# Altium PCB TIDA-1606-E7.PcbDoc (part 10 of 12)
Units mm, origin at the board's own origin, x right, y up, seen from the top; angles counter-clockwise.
Board outline 270 x 345 mm, 4 copper layers (Top Layer, Signal Layer 1, Signal Layer 2, Bottom Layer), stack 2.326 mm thick; 1282 components, 576 nets, 3628 pads, 4132 vias.
Unrouted connection lines stored in the file: 1719.
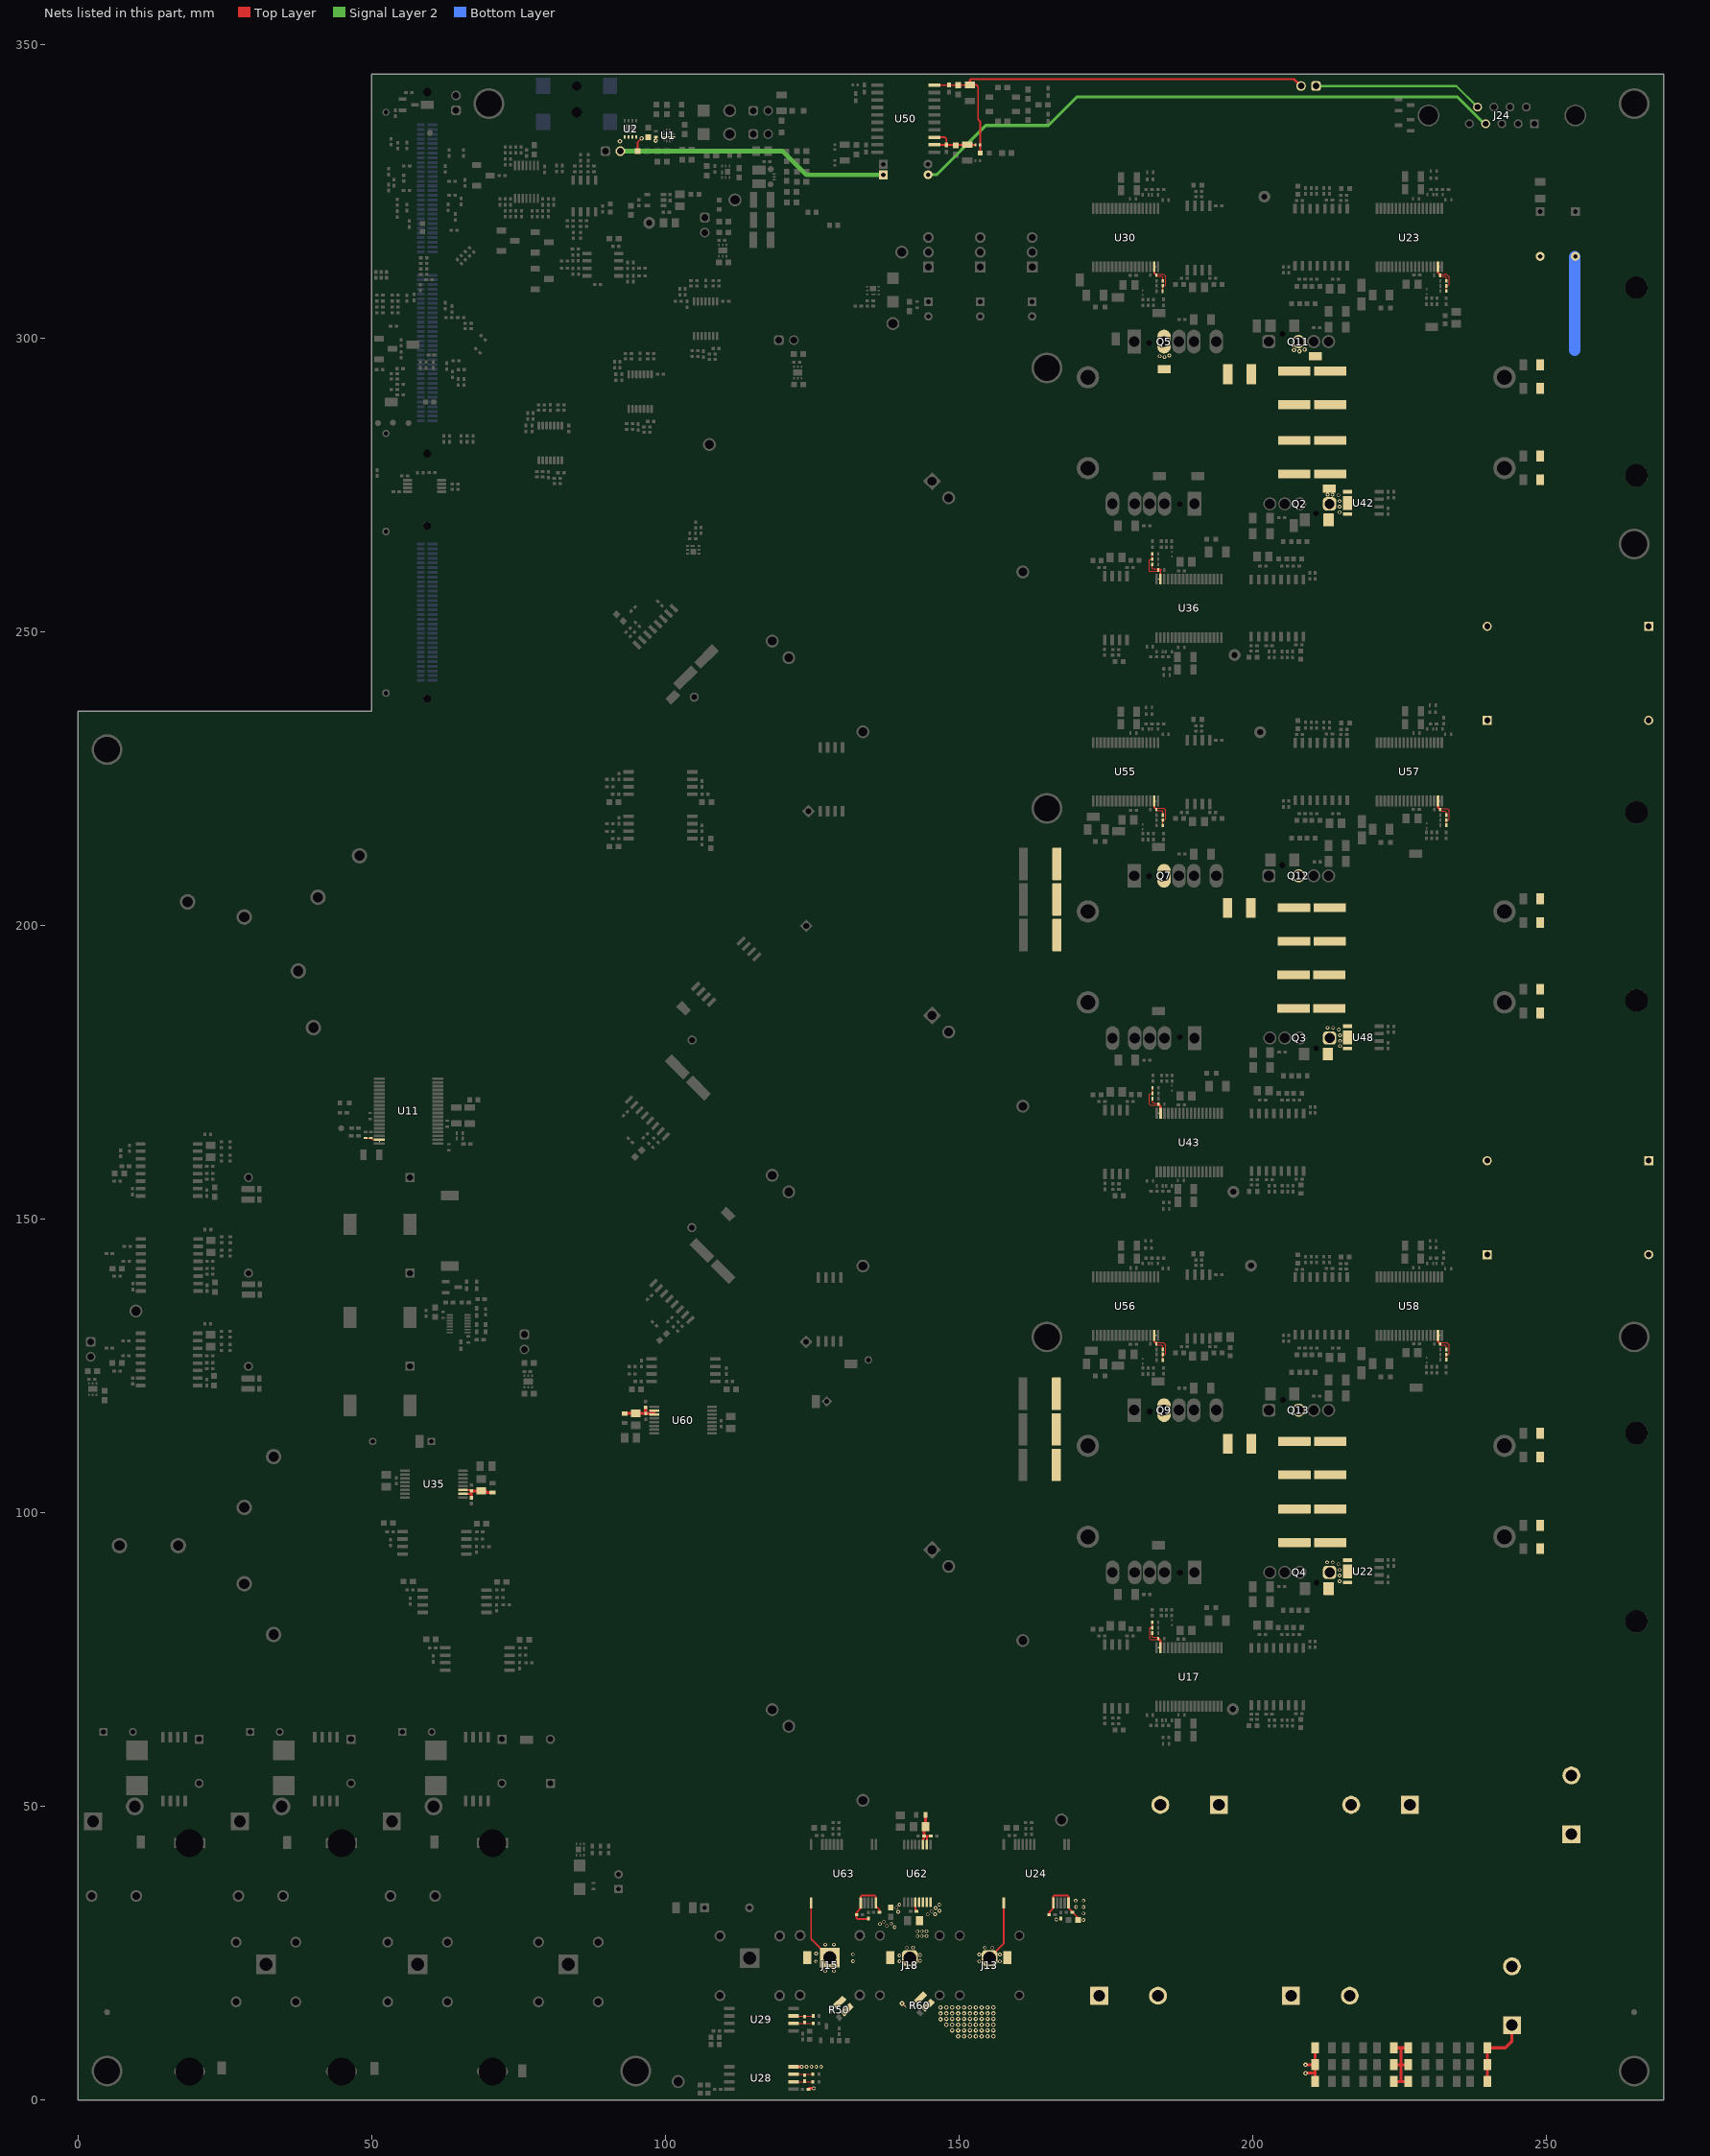
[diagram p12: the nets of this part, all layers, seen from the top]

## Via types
v1: diameter 0.762, hole 0.356, Top Layer to Bottom Layer, tented both sides, 2905 vias
v2: diameter 0.61, hole 0.356, Top Layer to Bottom Layer, tented both sides, 1212 vias
v3: diameter 0.864, hole 0.406, Top Layer to Bottom Layer, tented both sides, 15 vias

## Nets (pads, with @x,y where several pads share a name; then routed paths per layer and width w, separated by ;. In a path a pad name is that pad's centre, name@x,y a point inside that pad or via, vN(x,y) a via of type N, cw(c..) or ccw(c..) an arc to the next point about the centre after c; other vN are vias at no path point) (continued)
VDC+: C36.2 C37.2 C38.2 C39.2 C40.2 C41.2 C42.2 C43.2 C44.2 C45.2 C395.2 D8.1 D15.1 D17.1 J13.1 Q2.1 Q3.1 Q4.1 R41.2 R42.2 R43.2 TP29.1 TP65.1 U22.5 U22.6 U22.7 U24.1 U42.5 U42.6 U42.7 U48.5 U48.6 U48.7 | length 19.3
  Top Layer w0.305: J13.1@155.243,24.249 157.651,26.657 U24.1@157.651,33.6
  Top Layer w0.508: v1(209.05,4.594) 209.082,4.626 210.647,4.626 ; v1(209.05,6.06) R43.2@210.647,6.06 ; R41.2@210.647,3.192 210.647,4.626 ; R42.2@210.647,8.928 R43.2@210.647,6.06 ; 210.647,4.626 R43.2@210.647,6.06
  other v2: 154.619,22.5 155.918,22.5 153.5,23.639 157,23.639 153.5,24.841 157,24.841 154.451,26 155.75,26 214.853,88.39 214.853,89.354 214.853,90.295 214.653,91.295 212.729,91.595 213.67,91.595 214.921,179.498 214.921,180.393 214.921,181.334 214.718,182.334 212.793,182.634 213.734,182.634 214.853,270.432 214.853,271.359 214.853,272.3 214.653,273.3 212.795,273.412 213.639,273.412
VDC-: C46.1 C47.1 C48.1 C49.1 C50.1 C51.1 C52.1 C53.1 C54.1 C55.1 C396.1 C458.1 C459.1 C460.1 J4.2 Q11.2 Q12.2 Q13.2 R57.1 R58.1 R59.1 R60.I1 TP60.1 | length 29
  Top Layer w0.508: R57.1@239.992,3.192 R59.1@239.992,6.06 R58.1@239.992,8.928 243.044,8.928 244.189,10.073 C51.1@244.189,12.802
  Bottom Layer w2: 254.868,298.019 J4.2@254.868,313.9
  other v1: 149.9,10.9 150.9,10.895 151.9,10.9 152.9,10.901 153.9,10.901 154.9,10.9 155.9,10.9 148.892,11.9 149.9,11.9 150.9,11.895 151.9,11.9 152.9,11.901 153.9,11.901 154.9,11.9 155.9,11.9 147.9,12.857 148.892,12.863 149.9,12.863 150.9,12.857 151.9,12.863 152.9,12.864 153.9,12.864 154.9,12.863 155.9,12.863 146.9,13.8 147.9,13.857 150.9,13.857 148.892,13.863 149.9,13.863 151.9,13.863 152.9,13.864 153.9,13.864 154.9,13.863 155.9,13.863 146.9,14.8 147.9,14.795 148.892,14.8 149.9,14.8 150.9,14.795 151.9,14.8 152.9,14.801 153.9,14.801 154.9,14.8 155.9,14.8 146.9,15.8 147.9,15.795 148.892,15.8 149.9,15.8 150.9,15.795 151.9,15.8 152.9,15.801 153.9,15.801 154.9,15.8 155.9,15.8 208,297.846 207.077,298.046 208.896,298.133
VDC-_REF: C35.1 C176.1 C177.2 C222.2 C286.2 C446.2 C454.1 C456.1 C457.2 NT9.1 R21.2 R31.2 U24.2 U24.6 U28.4 U62.12 U62.13 U62.14 U62.15 U62.16 U63.2 U63.6 | length 27.2
  Top Layer w0.254: v1(140.348,16.5) NT9.1@140.82,16.027 ; U62.12@142.627,33.705 142.627,32.374 C286.2@142.801,32.2
  Top Layer w0.305: R31.2@132.598,31.5 132.598,31 132.698,30.9 C454.1@134.599,30.9 ; R31.2@132.598,31.582 132.598,31.974 133.298,32.674 U63.2@133.298,33.6 133.298,34.7 133.498,34.9 135.673,34.9 135.899,34.674 U63.6@135.899,33.6 135.899,33.073 136.498,32.474 C457.2@136.498,32 ; R21.2@165.4,31.582 165.4,31.974 166.1,32.674 U24.2@166.1,33.6 166.1,34.7 166.3,34.9 168.475,34.9 168.701,34.674 U24.6@168.701,33.6 168.701,32.715 170.301,31.115 C176.1@170.301,30.7 ; C35.1@167.401,30.9 C35.1@167.401,30.956
  Top Layer w0.5: U28.4@121.85,5.697 v2(123.283,5.697) ; C222.2@124.413,1.9 124.545,2.032 v2(125.349,2.032)
  other v2: 124.102,5.697 124.921,5.697 125.74,5.697 126.559,5.697 142.976,27.96 143.716,27.96 144.5,27.96 142.976,28.781 143.716,28.781 144.5,28.781 139.092,29.465 137.774,29.684 136.598,30 138.481,30.1 137.277,30.409 171.247,30.709 166.6,30.799 144.722,31.638 145.992,31.689 171.247,31.806 139.678,32.083 145.379,32.222 146.703,32.248 146.05,32.766 139.392,32.788 169.972,32.903 171.247,32.903 139.906,33.34 146.678,33.34 169.919,34 171.247,34
VDC_MID: C36.1 C37.1 C38.1 C39.1 C40.1 C41.1 C42.1 C43.1 C44.1 C45.1 C46.2 C47.2 C48.2 C49.2 C50.2 C51.2 C52.2 C53.2 C54.2 C55.2 C67.2 C71.2 C72.2 C73.2 C75.2 C76.2 C395.1 C396.2 C458.2 C459.2 C460.2 J5.2 Q5.2 Q7.2 Q9.2 R47.1 R48.1 R49.1 R50.I1 R51.2 R52.2 R53.2 R117.1 R118.1 R119.1 R120.1 R121.1 R122.1 R123.1 R124.1 R125.1 R126.1 R127.1 R128.1 TP33.1 | length 13.1
  Top Layer w0.508: R47.1@224.09,3.192 225.417,3.192 ; R49.1@224.09,6.06 225.31,6.06 ; R48.1@224.09,8.928 225.31,8.928 ; R51.2@226.542,3.192 225.417,3.192 ; R53.2@226.542,6.06 225.31,6.06 ; R52.2@226.542,8.928 225.31,8.928 ; 225.31,6.06 225.31,8.928 ; 225.31,6.06 225.31,3.299 225.417,3.192
  other v2: 185.039,296.841 184.226,297.002 185.826,297.099
VDC_MID_IN: J15.1 R50.I2 TP66.1 U63.1 | length 10.7
  Top Layer w0.305: U63.1@124.849,33.6 124.86,33.589 124.86,27.479 J15.1@128.065,24.274
  other v2: 127.287,22 128.728,22 125.691,23.621 131.985,23.666 131.985,24.867 125.729,25.004 127.287,26.522 128.726,26.522
VDC_NEG_IN: J18.1 R60.I2 TP67.1
  other v2: 141.203,22.497 142.325,22.5 139.906,23.666 143.406,23.75 139.906,24.665 143.406,24.75 141.203,26 142.231,26
VEEA_MID1: C244.2 C245.2 NT20.2 R256.1 R257.1 U30.35 | length 8.2
  Top Layer w0.203: R257.1@184.715,308.049 C245.2@184.715,308.976 185.093,308.976 185.2,309.083 185.2,310.602 184.828,310.974 183.842,310.974 C244.2@183.644,310.776 183.825,310.595 184.51,310.595 184.715,310.389 R256.1@184.715,309.818
  Top Layer w0.305: U30.35@183.278,312.215 183.278,311.142 C244.2@183.644,310.776
VEEA_MID2: C403.2 C404.2 NT23.2 R505.1 R506.1 U55.35 | length 8.2
  Top Layer w0.203: R506.1@184.717,217.104 C404.2@184.717,218.008 185.019,218.008 185.2,218.189 185.2,219.716 184.916,220 183.839,220 C403.2@183.646,219.807 183.838,219.615 183.838,219.6 184.626,219.6 184.717,219.509 R505.1@184.717,218.85
  Top Layer w0.305: U55.35@183.28,221.247 183.28,220.173 C403.2@183.646,219.807
VEEA_MID3: C411.2 C412.2 NT24.2 R513.1 R514.1 U56.35 | length 8.1
  Top Layer w0.203: R514.1@184.717,126.04 C412.2@184.717,127.013 185.053,127.013 185.2,127.16 185.2,128.6 184.8,129 183.834,129 C411.2@183.646,128.812 183.858,128.6 184.5,128.6 184.717,128.383 R513.1@184.717,127.855
  Top Layer w0.305: U56.35@183.28,130.251 183.28,129.178 C411.2@183.646,128.812
VEEA_SN_L1: C288.2 C289.2 NT21.2 R285.1 R286.1 U36.35 | length 8.7
  Top Layer w0.203: R285.1@182.942,261.535 182.942,260.798 183.757,260.798 C288.2@183.958,260.598 ; C289.2@182.942,262.373 182.464,262.373 182.464,260.398 183.758,260.398 C288.2@183.958,260.598 ; C289.2@182.943,262.468 R286.1@182.943,263.334 ; R286.1@182.99,263.21 R286.1@182.995,263.205 ; C288.2@183.961,260.6 C288.2@183.958,260.598
  Top Layer w0.305: U36.35@184.324,259.035 184.324,260.6
  Top Layer w0.4: C288.2@183.961,260.6 184.324,260.6
VEEA_SN_L2: C331.2 C332.2 NT22.2 R324.1 R325.1 U43.35 | length 8.3
  Top Layer w0.203: R324.1@182.984,170.569 182.984,170.028 183.188,169.823 183.808,169.823 C331.2@184,169.632 183.837,169.469 182.673,169.469 182.48,169.663 182.48,171.348 182.591,171.459 C332.2@182.984,171.459 ; C332.2@182.986,171.459 R325.1@182.986,172.405
  Top Layer w0.4: C331.2@184,169.632 184.366,169.266 U43.35@184.366,168.069
VEEA_SN_L3: C144.2 C145.2 NT18.2 R155.1 R156.1 U17.35 | length 8.3
  Top Layer w0.203: R155.1@182.944,79.572 182.944,78.921 183.035,78.829 183.765,78.829 C144.2@183.96,78.634 183.798,78.472 182.679,78.472 182.504,78.647 182.504,80.462 C145.2@182.945,80.462 R156.1@182.945,81.4
  Top Layer w0.4: C144.2@183.96,78.634 184.326,78.268 U17.35@184.326,77.074
VEEA_UCC_AEF: C93.2 NT17.2 R40.1 U11.35 | length 2.4
  Top Layer w0.203: R40.1@49.011,163.855 C93.2@49.9,163.855 50.184,163.571 U11.35@51.343,163.571
VEEA_VDC-1: C184.2 C185.2 NT19.2 R194.1 R195.1 U23.35 | length 7.9
  Top Layer w0.203: R195.1@233.012,308.095 C185.2@233.012,308.958 233.298,308.958 233.5,309.16 233.5,310.447 232.985,310.962 232.135,310.962 231.973,310.8 232.165,310.608 232.165,310.6 232.757,310.6 233.012,310.345 R194.1@233.012,309.803
  Top Layer w0.305: U23.35@231.607,312.215 231.607,311.166 C184.2@231.973,310.8
VEEA_VDC-2: C419.2 C420.2 NT25.2 R533.1 R534.1 U57.35 | length 8
  Top Layer w0.203: C420.2@233.014,217.127 R534.1@233.014,217.989 233.32,217.989 233.512,218.181 233.512,219.61 233.165,219.957 232.151,219.957 C419.2@231.975,219.781 232.184,219.572 232.802,219.572 233.014,219.36 R533.1@233.014,218.834
  Top Layer w0.4: U57.35@231.609,221.247 231.609,220.147 C419.2@231.975,219.781
VEEA_VDC-3: C427.2 C428.2 NT26.2 R541.1 R542.1 U58.35 | length 8.1
  Top Layer w0.203: R542.1@233.014,126.132 C428.2@233.014,126.994 233.394,126.994 233.5,127.1 233.5,128.628 233.128,129 232.19,129 C427.2@231.975,128.786 232.161,128.6 232.792,128.6 233.014,128.378 R541.1@233.014,127.839
  Top Layer w0.305: U58.35@231.609,130.251 231.609,129.152 C427.2@231.975,128.786
VIN_PWR: C1.1 C2.1 J1.2 J22.1 R1.2 U1.5 U2.1 U2.2 U2.3 U2.4 | length 48.9
  Top Layer w0.305: R1.2@95.302,331.9 95.302,333.381 v1(96.002,334.081) ; C2.1@98.602,334.292 C2.1@98.611,334.3
  Signal Layer 2 w0.762: J1.2@92.372,331.9 120.059,331.9 124.066,327.893 J22.1@137.16,327.893
  other v1: 92.302,333.6 98.414,333.707
VIN_PWR_CAN: J22.2 J24.4 | length 102.4
  Signal Layer 2 w0.508: J22.2@144.78,327.603 145.07,327.893 146.216,327.893 154.611,336.288 165.27,336.288 170.12,341.138 234.895,341.138 239.465,336.568 J24.4@239.718,336.568
VINN_DC-: C224.2 R243.2 U28.3 | length 3.3
  Top Layer w0.203: U28.3@121.85,4.427 R243.2@125.176,4.427
VINN_VMD: C273.2 R275.1 U29.3 | length 3.4
  Top Layer w0.203: U29.3@121.85,14.36 R275.1@125.218,14.36
VINP_DC-: C224.1 R238.2 U28.2 | length 3.3
  Top Layer w0.203: U28.2@121.85,3.157 123.771,3.157 123.78,3.166 123.828,3.119 R238.2@125.176,3.119
VINP_DC-_HAVOK: C292.1 C346.1 L11.1 R23.1 U62.2 U62.3 | length 7.8
  Top Layer w0.305: C292.1@144.085,45.014 144.577,45.014 ; U62.2@144.577,43.555 144.577,45.014 ; R23.1@145.242,45 145.228,45.014 144.577,45.014
  Top Layer w0.35: U62.3@143.927,43.555 143.927,44.425 144.085,44.582 C292.1@144.085,45.014
  Top Layer w0.5: C292.1@144.085,45.014 144.085,46.343 C346.1@144.342,46.6 L11.1@144.342,48.6
VINP_PCC_HAVOK: C285.1 C448.1 L14.1 R247.1 U35.2 U35.3 | length 7.8
  Top Layer w0.305: U35.2@65.56,103.275 67.02,103.275
  Top Layer w0.35: U35.3@65.56,103.925 66.862,103.925 C448.1@67.02,103.767 67.02,103.275 R247.1@67.02,102.61
  Top Layer w0.5: C448.1@67.02,103.767 68.348,103.767 69.433,103.767 69.69,103.51 L14.1@70.605,103.51
VINP_SN_HAVOK: C363.1 C364.1 L12.1 R76.1 U60.2 U60.3 | length 6.8
  Top Layer w0.35: U60.3@97.992,116.958 U60.3@98.15,116.8 U60.2@98.15,117.45
  Top Layer w0.5: L12.1@93.1,116.958 C364.1@95,116.958 C363.1@96.691,116.958 ; R76.1@96.68,118 96.68,116.969 C363.1@96.691,116.958 ; U60.3@97.992,116.958 C363.1@96.691,116.958
VINP_VMD: C273.1 R271.1 U29.2 | length 3.4
  Top Layer w0.203: U29.2@121.85,13.09 R271.1@125.218,13.09
VISOOUT: C380.1 C381.1 C382.1 FB18.1 U50.12 U50.13 | length 10.2
  Top Layer w0.305: U50.12@145.844,332.994 151.454,332.994 C382.1@151.463,333.003 151.494,332.971 FB18.1@152.841,332.971 ; U50.13@145.844,334.264 147.623,334.264 147.907,333.98 C380.1@147.907,332.995
VP_CAN: C374.1 C375.1 C376.1 D18.2 FB18.2 J25.2 U50.20 | length 76.8
  Top Layer w0.305: U50.20@145.844,343.154 C374.1@148.336,343.154 C375.1@149.9,343.154 151.876,343.154 C376.1@151.892,343.17 153.033,343.17 153.291,342.912 153.291,337.314 153.641,336.964 FB18.2@153.641,332.971 D18.2@153.641,331.605
  Top Layer w0.381: C376.1@151.876,343.154 151.876,343.923 152.122,344.17 207.107,344.17 J25.2@208.28,342.997
VP_CAN_SUBD: J24.9 J25.1 | length 29
  Signal Layer 2 w0.381: J25.1@210.82,342.997 234.744,342.997 J24.9@238.333,339.408
pads on no net: FID1.1 FID2.1 FID3.1 J3.MH1 J3.MH2 J13.2 J13.3 J13.4 J13.5 J14.2 J14.3 J14.4 J14.5 J15.2 J15.3 J15.4 J15.5 J16.2 J16.3 J16.4 J16.5 J17.2 J17.3 J17.4 J17.5 J18.2 J18.3 J18.4 J18.5 J19.3 J20.3 J21.3 J24.1 J24.8 J26.1 J26.2 J26.3 J26.4 J26.5 J26.6 J26.7 J26.8 J26.27 J26.28 J26.35 J26.43 J26.44 J26.48 J26.52 J26.54 J26.55 J26.58 J26.60 J26.77 J26.78 J26.80 J26.98 J26.113 J26.115 J26.116 J26.117 J26.118 J26.119 J26.120 J26.ALIGN1 J26.ALIGN2 J26.MH1 J26.MH2 J29. J29.3 J29.4 J29.5 J29.6 J29.7 J29.8 J29.9 J29.10 J29.11 J29.12 J29.13 J29.14 J29.15 J29.16 J29.17 J29.18 J29.19 J29.20 J29.21 J29.22 J29.25 J29.26 J29.27 J29.28 J29.29 J29.30 J29.31 J29.32 J29.33 J29.34 J29.35 J29.36 J29.37 J29.38 J29.39 J29.40 J29.41 J29.42 J29.43 J29.44 J29.45 J29.47 J29.48 J29.49 J29.50 J29.51 J29.52 J29.53 J29.54 J29.55 J29.56 J29.57 J29.58 J29.59 J29.60 J29.61 J29.62 J30.2 J30.3 J30.4 J30.5 L1.3 L1.4 L2.3 L2.4 L3.3 L3.4 LBL1.0 MP1.2 MP2.1 MP3.2 MP4.1 MP5.1 MP6.2 MP7. MP7.1 MP8. MP8.1 MP9. MP9.1 MP10. MP10.1 MP11. MP11.1 MP12. MP12.1 MP13. MP13.1 MP14. MP14.1 MP15. MP15.1 MP16. MP16.1 MP17. MP17.1 MP18. MP19. MP20. MP21. MP22. MP23. Q1.0 Q14.0 Q15.0 R435.1 R437.1 RN1.1 RN1.2 RN1.3 RN1.7 RN1.8 RN2.1 RN2.2 RN2.3 RN2.7 RN2.8 RN3.1 RN3.2 RN3.3 RN3.7 RN3.8 RN4.1 RN4.2 RN4.3 RN4.7 RN4.8 RN5.1 RN5.2 RN5.3 RN5.7 RN5.8 RN6.1 RN6.2 RN6.3 RN6.7 RN6.8 U2.9 U3.2 U5.7@122.138,294.218 U5.7@123.038,294.218 U6.7@2.1,121.112 U6.7@3,121.112 U7.7@76.24,122.401 U7.7@77.14,122.401 U10.3 U12.1 U12.3 U12.12 U14.4 U15.4 U16.4 U19.16 U22.2 U24.7 U24.8 U24.12 U24.13 U24.15 U25.16 U26.16 U27.16 U38.16 U42.2 U45.16 U48.2 U50.2 U50.7 U50.14 U54.7 U63.7 U63.8 U63.12 U63.13 U63.15 U64.3 U65.3 U66.7@109.367,314.983 U66.7@110.267,314.983

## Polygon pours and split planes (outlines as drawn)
VIN_PWR on Signal Layer 2 "Bottom Layer-VIN_PWR" (solid, pour order 2258): 95.411,333.791 95.411,334.809 99.067,334.809 99.067,334.448 99.068,334.15 99.07,333.288 95.914,333.288
VIN_PWR on Signal Layer 2 "Bottom Layer-VIN_PWR" (solid, pour order 2257): 92.244,334.6 92.937,334.6 92.937,334 92.937,332.78 93.256,332.461 93.256,331.04 91.502,331.04 91.502,333.859
GND on Signal Layer 2 "SIGNAL_LAYER_2_GND_P2154" (solid, remove dead copper, pour order 2154): 92 vertices, not listed, extent 0,0.407 270.1,345.207
GND on Signal Layer 2 "SIGNAL_LAYER_2_GND_P2146" (solid, remove dead copper, pour order 2146): 20 vertices, not listed, extent 134.152,99.045 233.583,183.876
GND on Signal Layer 2 "SIGNAL_LAYER_2_GND_P2147" (solid, remove dead copper, pour order 2147): 17 vertices, not listed, extent 145,42.807 236.2,92.808
VDC- on Signal Layer 2 "SIGNAL_LAYER_2_VDC-_P2252" (solid, remove dead copper, pour order 2252): 146.009,16.7 145.994,16.685 145.998,13.232 149.13,10.1 156.9,10.1 156.9,16.7
GND_ISO_CAN on Signal Layer 2 "SIGNAL_LAYER_2_GND_ISO_CAN_P2243" (solid, remove dead copper, pour order 2243): 164.143,334.813 168.33,339 219.184,339 223.479,334.813 259.08,334.813 259.08,345 167.64,345 144.794,345 144.794,327.576 156.906,327.576
VDC-_REF on Signal Layer 2 "Top Layer-REF_SN_L1" (solid, remove dead copper, pour order 2241): 171.75,29.584 146.009,29.584 146.009,27.5 135.64,27.5 135.64,35 171.75,35
AMC_HGND_L2 on Signal Layer 2 "Bottom Layer-AMC_HGND_L2" (solid, pour order 2240): 19.354,132.698 26.954,132.698 26.954,120.298 19.354,120.298
AMC_HGND_L3 on Signal Layer 2 "Bottom Layer-AMC_HGND_L3" (solid, pour order 2237): 19.354,148.771 26.954,148.771 26.954,136.371 19.354,136.371
AMC_HGND_L1 on Signal Layer 2 "Bottom Layer-AMC_HGND_L1" (solid, pour order 2236): 19.331,164.956 26.931,164.956 26.931,152.556 19.331,152.556
VDC-_REF on Signal Layer 2 "Signal Layer 2-VDC-_REF" (solid, pour order 2233): 19 vertices, not listed, extent 121,0 145.5,29.416
V_PCC_N on Signal Layer 2 "Signal Layer 1-V_PCC_N" (solid, pour order 2231): 45.2,82.129 68.029,59.3 81.255,59.3 81.255,63.2 72.335,63.2 63.535,72 63.554,72.019 63.554,77.719 59.555,81.718 59.559,88.1 56.455,91.204 56.455,108.523 50.355,108.523 50.355,87.284
REF_MID3 on Signal Layer 2 "Bottom Layer-REF_MID1" (solid, remove dead copper, pour order 2153): 121,16.8 121,9.657 132.105,9.657 132.105,10.695 126,16.8
VDC-_REF on Signal Layer 2 "Top Layer-REF_SN_L1" (solid, remove dead copper, pour order 2230): 171.563,30 140.284,30 140.284,27.5 138.5,27.5 138.5,35 171.563,35
+5VISO_DC- on Signal Layer 2 "Top Layer-REF_SN_L1" (solid, remove dead copper, pour order 2229): 169.4,29.416 142.24,29.416 142.24,27.5 140.208,27.5 140.208,30.988 169.4,30.988
-4V_SN_L2 on Signal Layer 2 "SIGNAL_LAYER_2_-4V_SN_L2_P2058" (solid, remove dead copper, pour order 2058): 17 vertices, not listed, extent 172.694,167.085 211.178,180.753
-4V_SN_L3 on Signal Layer 2 "SIGNAL_LAYER_2_-4V_SN_L3_P2057" (solid, remove dead copper, pour order 2057): 17 vertices, not listed, extent 172.594,76.219 211.078,89.887
AEF_CHK_3 on Signal Layer 2 "Bottom Layer-AEF_CHK_3" (solid, pour order 2109): 18 vertices, not listed, extent 16,139.496 48.7,206.3
-4V_MID3 on Signal Layer 2 "Signal Layer 2--4V_SN_L1" (solid, remove dead copper, pour order 2204): 169.813,122.397 196.279,122.397 196.279,131.147 169.813,131.147
-4V_VDC-3 on Signal Layer 2 "Signal Layer 2--4V_SN_L1" (solid, remove dead copper, pour order 2203): 205.587,122.486 234.71,122.486 234.71,131.235 205.587,131.235
-4V_MID2 on Signal Layer 2 "Signal Layer 2--4V_SN_L1" (solid, remove dead copper, pour order 2202): 169.88,213.484 196.347,213.484 196.347,222.234 169.88,222.234
-4V_VDC-2 on Signal Layer 2 "Signal Layer 2--4V_SN_L1" (solid, remove dead copper, pour order 2201): 204.691,213.442 233.814,213.442 233.814,222.192 204.691,222.192
-4V_VDC-1 on Signal Layer 2 "Signal Layer 2--4V_SN_L1" (solid, remove dead copper, pour order 2200): 204.88,304.453 234.003,304.453 234.003,313.202 204.88,313.202
-4V_MID1 on Signal Layer 2 "Signal Layer 2--4V_SN_L1" (solid, remove dead copper, pour order 2199): 169.872,304.453 196.339,304.453 196.339,313.202 169.872,313.202
V_SN_N on Signal Layer 2 "Top Layer-No Net" (solid, remove dead copper, pour order 2195): 43 vertices, not listed, extent 103.777,114 161.798,227.5
VDC+ on Signal Layer 2 "Signal Layer 2-VDC+ 2" (solid, remove dead copper, pour order 2187): 17 vertices, not listed, extent 211.888,71 246.796,125.187
CHK_1 on Signal Layer 2 "Top Layer-CHK_1" (solid, pour order 2181): 34,152.07 34,148.166 28.921,148.166 27.94,149.147 27.94,153 30.3,153 30.3,152.77 30.999,152.07
RLAY_1 on Signal Layer 2 "SIGNAL_LAYER_2_RLAY_1_P2178" (solid, remove dead copper, pour order 2178): 9.3,96.984 2.005,96.984 0.004,94.984 0.004,44.485 5.505,44.482 5.505,65.066 11.505,71.066 11.505,94.779
V_PCC_L3 on Signal Layer 2 "SIGNAL_LAYER_2_V_PCC_L3_P2173" (solid, pour order 2173): 58.978,52.515 70.86,52.515 70.86,55.015 73.526,55.015 73.526,42.015 58.978,42.015
V_PCC_L2 on Signal Layer 2 "SIGNAL_LAYER_2_V_PCC_L2_P2171" (solid, pour order 2171): 32.901,52.515 45.333,52.515 45.333,55.015 47.999,55.015 47.999,42.015 32.901,42.015
V_PCC_L1 on Signal Layer 2 "SIGNAL_LAYER_2_V_PCC_L1_P2167" (solid, pour order 2167): 8,52.5 19.346,52.5 19.346,55 22.012,55 22.012,42 8,42
PCC_L3 on Signal Layer 2 "Top Layer-PCC_L1" (solid, pour order 2162): 86.985,25.978 65.985,25.978 65.985,1.978 86.985,1.978
PCC_L2 on Signal Layer 2 "Top Layer-PCC_L1" (solid, pour order 2158): 62.039,25.978 41.039,25.978 41.039,1.978 62.039,1.978
PCC_L1 on Signal Layer 2 "Top Layer-PCC_L1" (solid, pour order 2156): 36,26 15,26 15,2 36,2
VDC+ on Signal Layer 2 "Signal Layer 2-VDC+ 2" (solid, remove dead copper, pour order 1947): 19 vertices, not listed, extent 211.838,162.901 246.746,216.043
no net on Signal Layer 2 "Signal Layer 2-No Net 1" (solid, pour order 2138): 97.437,109.5
no net on Signal Layer 2 "Signal Layer 2-No Net 2" (solid, pour order 2137): 97.539,109.5
VDC+ on Signal Layer 2 "Signal Layer 2-VDC+" (solid, remove dead copper, pour order 1903): 19 vertices, not listed, extent 149.243,2.006 268,296.35
VDC+ on Signal Layer 2 "SIGNAL_LAYER_2_VDC+_P2135" (solid, pour order 2135): 268.5,142.987 268.5,144.987 267.624,144.987 267.624,142.987
VDC+ on Signal Layer 2 "SIGNAL_LAYER_2_VDC+_P2134" (solid, pour order 2134): 268.5,234.001 268.5,236.001 267.624,236.001 267.624,234.001
+5V on Signal Layer 2 "SIGNAL_LAYER_2_+5V_P2129" (solid, remove dead copper, pour order 2129): 110.802,326 114.002,326 114.002,327.1 117.102,327.1 117.102,325.6 116.454,324.952 116.454,315.5 112.402,315.5 112.402,321 110.802,321
I_SN_L3+ on Signal Layer 2 "Signal Layer 2-I_SN_L3+" (solid, pour order 2111): 127.023,66.723 120.205,59.905 99.442,80.669 106.296,87.45
I_SN_L1+ on Signal Layer 2 "Top Layer-I_SN_L1+" (solid, remove dead copper, pour order 2107): 115.11,250.974 110.446,246.31 110.278,246.31 109.844,246.744 106.486,243.386 112.765,237.106 116.306,237.106 124.64,245.44 119.106,250.974
DESAT_BOT_L3 on Signal Layer 2 "Bottom Layer-DESAT_BOT_L2" (solid, remove dead copper, pour order 2103): 140.892,94.242 145.892,99.242 153.883,91.251 148.882,86.251
DESAT_BOT_L2 on Signal Layer 2 "Bottom Layer-DESAT_BOT_L2" (solid, remove dead copper, pour order 2102): 141.092,185.608 146.092,190.608 154.083,182.618 149.082,177.617
DESAT_BOT_L1 on Signal Layer 2 "SIGNAL_LAYER_2_DESAT_BOT_L1_P2099" (solid, remove dead copper, pour order 2099): 140.993,276.173 146.71,281.89 154.701,273.899 148.984,268.182
RLAY_3 on Signal Layer 2 "SIGNAL_LAYER_2_RLAY_3_P2077" (solid, pour order 2077): 51.9,60.466 51.9,44.516 56,44.516 56,51.166 56.452,51.618 56.452,66.914 42.7,80.666 32,80.666 32,75.166 42.6,64.566 47.8,64.566
RLAY_2 on Signal Layer 2 "Signal Layer 2-RLAY_2" (solid, pour order 2072): 19 vertices, not listed, extent 16.2,44.515 39.8,111.3
-4V_SN_L1 on Signal Layer 2 "SIGNAL_LAYER_2_-4V_SN_L1_P2059" (solid, remove dead copper, pour order 2059): 17 vertices, not listed, extent 172.837,258.159 211.321,271.826
I_SN_L2+ on Signal Layer 2 "Top Layer-I_SN_L2+" (solid, remove dead copper, pour order 1939): 103.548,173.333 115.52,161.361 115.52,156.541 121.163,150.898 126.188,155.923 126.188,161.82 110.44,177.568 107.782,177.568
DESAT_BOT_L3 on Signal Layer 2 "Signal Layer 2-DESAT_BOT_L3" (solid, remove dead copper, pour order 1927): 205.384,91.34 202.567,91.34 199.578,94.329 199.578,118.894 203.992,118.894 203.992,95.525 205.254,94.263 208.564,94.258 209.326,93.496 209.326,91.498 209.326,87.642 206.494,87.642 206.494,90.23
L3_MID_DRAIN on Signal Layer 2 "Signal Layer 2-L3_MID_DRAIN" (solid, remove dead copper, pour order 1926): 184.458,103.678 187.222,103.678 188.99,101.911 188.99,88.176 189.26,87.906 192.562,87.906 192.816,88.16 192.96,88.16 192.96,111.583 192.029,112.514 183.163,112.514 181.132,114.545 181.132,119.656 177.322,119.656 177.322,110.814
L2_MID_DRAIN on Signal Layer 2 "Signal Layer 2-L2_MID_DRAIN" (solid, remove dead copper, pour order 1925): 184.378,194.61 187.142,194.61 188.91,192.843 188.91,179.108 189.18,178.838 192.482,178.838 192.736,179.092 192.88,179.092 192.88,202.515 191.949,203.446 183.083,203.446 181.052,205.477 181.052,210.588 177.242,210.588 177.242,201.746
DESAT_BOT_L2 on Signal Layer 2 "Signal Layer 2-DESAT_BOT_L2" (solid, remove dead copper, pour order 1924): 205.304,182.272 202.487,182.272 199.498,185.261 199.498,209.826 203.912,209.826 203.912,186.457 205.174,185.195 208.484,185.19 209.246,184.428 209.246,182.43 209.246,178.653 205.69,178.653 205.69,181.886
DESAT_BOT_L1 on Signal Layer 2 "Signal Layer 2-DESAT_BOT_L1" (solid, remove dead copper, pour order 1914): 205.304,273.204 202.487,273.204 199.498,276.193 199.498,300.758 204.2,300.758 204.2,277.101 205.174,276.127 208.484,276.122 209.4,275.206 209.4,269.748 205.69,269.748 205.69,272.818
L1_MID_DRAIN on Signal Layer 2 "Signal Layer 2-L1_MID_DRAIN" (solid, remove dead copper, pour order 1913): 184.378,285.542 187.142,285.542 188.91,283.775 188.91,270.04 189.18,269.77 192.482,269.77 192.736,270.024 192.88,270.024 192.88,293.447 191.949,294.378 183.083,294.378 181.1,296.361 181.1,301.52 177.242,301.52 177.242,292.678
no net on Signal Layer 2 "Signal Layer 2-No Net" (solid, remove dead copper, pour order 1902): 247.6,50.06
GND on Bottom Layer "BOTTOM_LAYER_GND_P2150" (solid, remove dead copper, pour order 2150): 37 vertices, not listed, extent -0.079,118.007 270.021,345.217
VIN_PWR on Bottom Layer "Bottom Layer-VIN_PWR" (solid, pour order 2122): 92.244,334.6 92.937,334.6 92.937,334 92.937,332.78 93.256,332.461 93.256,331.04 91.502,331.04 91.502,333.859
VIN_PWR on Bottom Layer "Bottom Layer-VIN_PWR" (solid, pour order 2121): 95.411,333.791 95.411,334.809 99.067,334.809 99.067,334.448 99.068,334.15 99.07,333.288 95.914,333.288
+12V_OUT on Bottom Layer "Bottom Layer-+12V_OUT" (solid, pour order 2120): 116.004,336 115.966,339.9 113.941,339.9 113.941,336 109.802,336 109.802,335.309 104.054,335.309 104.05,333.644 116.004,333.644
+12V_FAN on Bottom Layer "BOTTOM_LAYER_+12V_FAN_P2256" (solid, remove dead copper, pour order 2256): 127.24,318.668 128.768,318.668 128.768,316.679 127.24,316.679
+12V on Bottom Layer "BOTTOM_LAYER_+12V_P2254" (solid, remove dead copper, pour order 2254): 124.943,320.929 126.47,320.929 126.47,318.94 124.943,318.94
GND on Bottom Layer "BOTTOM_LAYER_GND_P2149" (solid, remove dead copper, pour order 2149): 234.2,230.452 234.299,230.452 234.299,239.978 234.299,249.997 234.229,250.067 225.081,250.067 225.081,274.697 221.081,274.696 221.081,250.097 209.928,250.096 178.849,250.096 159.205,230.452 171.517,230.452 171.517,230.256 234.2,230.255
GND on Bottom Layer "BOTTOM_LAYER_GND_P2151" (solid, remove dead copper, pour order 2151): 52 vertices, not listed, extent 58.6,0.216 233.461,183.871
GND on Bottom Layer "BOTTOM_LAYER_GND_P2152" (solid, remove dead copper, pour order 2152): 154.513,42.797 170.053,42.797 170.053,50.578 175.671,56.196 236.181,56.197 236.181,68.297 225.102,68.297 225.102,92.777 225.081,92.798 221.083,92.798 221.083,68.297 173.902,68.297 173.902,68.036 171.4,68.036 171.4,59.683
VDC+ on Bottom Layer "Bottom Layer-VDC+" (solid, pour order 2250): 211.981,274 215.981,274 215.981,270 211.981,270
VDC+ on Bottom Layer "Bottom Layer-VDC+ 1" (solid, pour order 2249): 212,183.004 216,183.004 216,179.004 212,179.004
VDC+ on Bottom Layer "Bottom Layer-VDC+ 2" (solid, pour order 2248): 212,92 216,92 216,88 212,88
no net on Bottom Layer "Bottom Layer-No Net 7" (solid, pour order 2247): 215.993,92.03
no net on Bottom Layer "Bottom Layer-No Net 8" (solid, pour order 2246): 212,92
no net on Bottom Layer "Bottom Layer-No Net 9" (solid, pour order 2245): 215.993,92.03
VDC-_REF on Bottom Layer "Top Layer-REF_SN_L1" (solid, remove dead copper, pour order 2242): 171.75,29.584 145.337,29.584 145.337,27.5 138,27.5 138,35 171.75,35
+5VISO_DC- on Bottom Layer "Bottom Layer-+5VISO_DC-" (solid, pour order 2234): 18 vertices, not listed, extent 121,0 145.5,29.852
+5VISO_PCC on Bottom Layer "Signal Layer 1-V_PCC_N" (solid, pour order 2232): 63.55,77.71 63.55,77.65 56.608,70.708 45.196,82.12 50.351,87.275 50.351,108.523 56.451,108.523 56.451,91.195 59.556,88.091 59.551,81.709
-4V_SN_L2 on Bottom Layer "Signal Layer 2--4V_SN_L1" (solid, remove dead copper, pour order 2017): 172.622,173.792 172.622,167.277 211.052,167.277 211.052,173.792
+15V_SN_L2 on Bottom Layer "Signal Layer 2-+15V_SN_L1" (solid, remove dead copper, pour order 2016): 172.622,176.034 172.622,173.792 211.038,173.792 211.038,176.034
-4V_SN_L3 on Bottom Layer "Signal Layer 2--4V_SN_L1" (solid, remove dead copper, pour order 2031): 172.583,82.794 172.583,76.279 211.013,76.279 211.013,82.794
+15V_SN_L3 on Bottom Layer "Signal Layer 2-+15V_SN_L1" (solid, remove dead copper, pour order 2030): 172.583,85.036 172.583,82.794 210.999,82.794 210.999,85.036
AEF_CHK_2 on Bottom Layer "Bottom Layer-AEF_CHK_2" (solid, pour order 2080): 41.6,184 42.6,183 47.068,183.032 54.3,175.8 54.3,140.736 43.264,129.7 36.064,122.5 28.066,122.5 28.066,126.772 45.4,144.106 45.4,175.1 38.78,181.72 38.78,184
AEF_CHK_3 on Bottom Layer "Bottom Layer-AEF_CHK_3" (solid, pour order 2083): 27.4,139.6 37,139.6 42.4,145 42.4,179.2 22.3,199.3 22.3,204.1 20.1,206.3 17.55,206.3 16,204.75 16,191.2 34.4,172.8 34.4,145.612 31.588,142.8 27.4,142.8
V_SN_N on Bottom Layer "Top Layer-No Net" (solid, remove dead copper, pour order 2192): 155.313,201.678 155.313,213.342 161.798,213.342 161.798,201.678
REF_MID3 on Bottom Layer "Bottom Layer-REF_MID1" (solid, remove dead copper, pour order 2190): 121,16.8 121,9.657 132.105,9.657 132.105,10.695 126,16.8
VDC- on Bottom Layer "Bottom Layer-VDC- 2" (solid, remove dead copper, pour order 2188): 230,81.548 241.579,69.969 241.579,76.964 241.654,77.04 241.654,94.81 241.654,119.493 206.746,119.493 206.746,102.482 214.419,94.81 225.127,94.81 230,89.937
CHK_1 on Bottom Layer "Top Layer-CHK_1" (solid, pour order 2182): 34,152.07 34,148.166 28.921,148.166 27.94,149.147 27.94,153 30.3,153 30.3,152.77 30.999,152.07
no net on Bottom Layer "Bottom Layer-No Net 2" (solid, pour order 2180): 56.04,46.31
RLAY_1 on Bottom Layer "BOTTOM_LAYER_RLAY_1_P2179" (solid, remove dead copper, pour order 2179): 9.3,96.984 2.005,96.984 0.004,94.984 0.004,44.485 5.505,44.482 5.505,65.066 11.505,71.066 11.505,94.779
V_PCC_L3 on Bottom Layer "BOTTOM_LAYER_V_PCC_L3_P2174" (solid, pour order 2174): 59,52.515 70.86,52.515 70.86,55.015 73.526,55.015 73.526,42.015 59,42.015
V_PCC_L2 on Bottom Layer "BOTTOM_LAYER_V_PCC_L2_P2172" (solid, pour order 2172): 32.901,52.515 45.333,52.515 45.333,55.015 47.999,55.015 47.999,42.015 32.901,42.015
V_PCC_L1 on Bottom Layer "BOTTOM_LAYER_V_PCC_L1_P2168" (solid, pour order 2168): 7.9,52.5 19.34,52.5 19.34,55 22.006,55 22.006,42 7.9,42
PCC_L3 on Bottom Layer "Top Layer-PCC_L1" (solid, pour order 2163): 86.985,25.978 65.985,25.978 65.985,1.978 86.985,1.978
PCC_L2 on Bottom Layer "Top Layer-PCC_L1" (solid, pour order 2159): 62.039,25.978 41.039,25.978 41.039,1.978 62.039,1.978
PCC_L1 on Bottom Layer "Top Layer-PCC_L1" (solid, pour order 2157): 36,26 15,26 15,2 36,2
I_SN_L1+ on Bottom Layer "Top Layer-I_SN_L1+" (solid, remove dead copper, pour order 1938): 117.055,250.974 111.334,245.253 108.364,248.224 105.019,244.878 104.993,244.878 112.765,237.106 117.506,237.106 125.24,244.84 119.106,250.974
DESAT_BOT_L1 on Bottom Layer "Bottom Layer-DESAT_BOT_L1" (solid, remove dead copper, pour order 1907): 19 vertices, not listed, extent 141.85,268.2 209.5,300.959
+15V_MID2 on Bottom Layer "Signal Layer 2-+15V_SN_L1" (solid, remove dead copper, pour order 1966): 169.88,215.5 169.88,213.484 194.321,213.484 194.321,215.5
-4V_MID2 on Bottom Layer "Signal Layer 2--4V_SN_L1" (solid, remove dead copper, pour order 1965): 169.88,215.5 194.321,215.5 194.321,222.241 169.88,222.241
VDC- on Bottom Layer "Bottom Layer-VDC-" (solid, remove dead copper, pour order 1904): 20 vertices, not listed, extent 146.331,2.562 268,301.8
I_SN_L3- on Bottom Layer "Bottom Layer-I_SN_L3-" (solid, remove dead copper, pour order 1936): 99.4,193.8 114.5,178.7 124.2,188.4 110.9,201.7 33.3,201.7 30.1,204.9 27.404,204.9 25,202.496 25,199.9 31.1,193.8
DESAT_BOT_L2 on Bottom Layer "Bottom Layer-DESAT_BOT_L2" (solid, remove dead copper, pour order 1917): 19 vertices, not listed, extent 141.982,177.443 209.358,210.715
I_SN_L2- on Bottom Layer "Top Layer-I_SN_L2-" (solid, remove dead copper, pour order 2085): 102.122,188.078 96.4,193.8 35.692,193.8 35.692,190.923 41.715,184.9 91.949,184.9 95.988,180.861 103.112,173.828 103.151,173.828 107.43,178.107 107.43,182.77
+15V_MID3 on Bottom Layer "Signal Layer 2-+15V_SN_L1" (solid, remove dead copper, pour order 2042): 169.88,124.504 169.88,122.488 194.565,122.488 194.565,124.504
-4V_MID3 on Bottom Layer "Signal Layer 2--4V_SN_L1" (solid, remove dead copper, pour order 2041): 171.4,131.245 171.4,127.488 169.88,125.968 169.88,124.504 194.565,124.504 194.565,131.245
I_SN_L3+ on Bottom Layer "Bottom Layer-I_SN_L3+" (solid, remove dead copper, pour order 1933): 103.98,76.122 98.801,81.301 113.186,95.686 113.186,136.74 107.664,142.262 114.098,148.697 114.504,148.697 126,137.201 126,98.142
DESAT_BOT_L3 on Bottom Layer "Bottom Layer-DESAT_BOT_L3" (solid, remove dead copper, pour order 1919): 19 vertices, not listed, extent 141.995,86.759 209.5,119.705
CAN_GND1 on Bottom Layer "BOTTOM_LAYER_CAN_GND1_P2142" (solid, remove dead copper, pour order 2142): 130.65,343.916 137.194,343.916 137.194,329.81 130.65,329.81
GND_ISO_CAN on Bottom Layer "BOTTOM_LAYER_GND_ISO_CAN_P2140" (solid, remove dead copper, pour order 2140): 164.143,334.813 168.33,339 219.184,339 223.479,334.813 259.08,334.813 259.08,345 167.64,345 144.794,345 144.794,327.576 156.906,327.576
AUX_IN_PWR on Bottom Layer "BOTTOM_LAYER_AUX_IN_PWR_P2128" (solid, remove dead copper, pour order 2128): 87.067,333.985 87.702,333.35 87.702,332.6 89.302,331 90.702,331 90.702,332.722 86.025,337.4 86,337.375 83.202,337.375 83.202,344.614 77.412,344.614 77.412,333.985
VDC- on Bottom Layer "BOTTOM_LAYER_VDC-_P2133" (solid, pour order 2133): 268.5,159 268.5,161 267.624,161 267.624,159
VDC- on Bottom Layer "BOTTOM_LAYER_VDC-_P2132" (solid, pour order 2132): 268.5,250 268.5,252 267.624,252 267.624,250
+5V on Bottom Layer "BOTTOM_LAYER_+5V_P2127" (solid, remove dead copper, pour order 2127): 110.802,326 114.002,326 114.002,327.1 117.102,327.1 117.102,325.6 116.454,324.952 116.454,315.5 112.402,315.5 112.402,321 110.802,321
V_SN_N on Bottom Layer "Top Layer-No Net" (solid, remove dead copper, pour order 1984): 157,108.215 153.774,111.441 146.666,111.441 132.254,125.854 134.75,128.35 147.435,115.665 157,115.665 157,123.114 161.679,123.111 161.679,108.215
no net on Bottom Layer "Bottom Layer-No Net 4" (solid, pour order 2114): 115.4,191.835
no net on Bottom Layer "Bottom Layer-No Net 5" (solid, pour order 2113): 109.651,186.126
no net on Bottom Layer "Bottom Layer-No Net 6" (solid, pour order 2112): 99.668,83.174
VDC_MID on Bottom Layer "Bottom Layer-VDC_MID" (solid, pour order 2108): 185.013,301.462 185.013,300 186.39,300 186.39,296.361 183.636,296.361 183.636,301.462
AMC_HGND_L2 on Bottom Layer "Bottom Layer-AMC_HGND_L2" (solid, pour order 2088): 19.312,132.698 26.912,132.698 26.912,120.298 19.312,120.298
AMC_HGND_L1 on Bottom Layer "Bottom Layer-AMC_HGND_L1" (solid, pour order 2090): 19.312,164.956 26.912,164.956 26.912,152.556 19.312,152.556
AMC_HGND_L3 on Bottom Layer "Bottom Layer-AMC_HGND_L3" (solid, pour order 2086): 19.354,148.771 26.954,148.771 26.954,136.371 19.354,136.371
AEF_CHK_1 on Bottom Layer "BOTTOM_LAYER_AEF_CHK_1_P2084" (solid, pour order 2084): 17 vertices, not listed, extent 7.26,155.146 50.1,220.81
RLAY_3 on Bottom Layer "Bottom Layer-RLAY_3" (solid, pour order 2076): 51.9,60.5 51.9,44.516 55.978,44.516 55.978,51.378 56.51,51.91 56.51,66.89 42.6,80.8 31.9,80.8 31.9,75.3 42.5,64.7 47.7,64.7
no net on Bottom Layer "Bottom Layer-No Net 2" (solid, pour order 2071): 30.157,46.385
RLAY_2 on Bottom Layer "Bottom Layer-RLAY_2" (solid, pour order 2070): 19 vertices, not listed, extent 16.2,44.516 39.8,111.3
no net on Bottom Layer "Bottom Layer-No Net 3" (solid, pour order 2069): 26.2,66.229
-4V_MID1 on Bottom Layer "Signal Layer 2--4V_SN_L1" (solid, remove dead copper, pour order 2008): 169.878,306.468 194.319,306.468 194.319,313.209 169.878,313.209
+15V_VDC-3 on Bottom Layer "Signal Layer 2-+15V_SN_L1" (solid, remove dead copper, pour order 2056): 234.705,122.418 234.705,124.661 206,124.661 206,122.418
-4V_VDC-3 on Bottom Layer "Signal Layer 2--4V_SN_L1" (solid, remove dead copper, pour order 2055): 234.705,124.661 234.705,131.175 205.5,131.175 205.5,124.661
+15V_MID1 on Bottom Layer "Signal Layer 2-+15V_SN_L1" (solid, remove dead copper, pour order 2009): 169.878,306.468 169.878,304.453 194.319,304.453 194.319,306.468
-4V_VDC-1 on Bottom Layer "Signal Layer 2--4V_SN_L1" (solid, remove dead copper, pour order 1990): 234.003,306.695 234.003,313.209 204.798,313.209 204.798,306.695
+15V_VDC-1 on Bottom Layer "Signal Layer 2-+15V_SN_L1" (solid, remove dead copper, pour order 1991): 234.003,304.453 234.003,306.695 205.298,306.695 205.298,304.453
-4V_VDC-2 on Bottom Layer "Signal Layer 2--4V_SN_L1" (solid, remove dead copper, pour order 1972): 234.005,215.727 234.005,222.241 204.8,222.241 204.8,215.727
+15V_VDC-2 on Bottom Layer "Signal Layer 2-+15V_SN_L1" (solid, remove dead copper, pour order 1971): 234.005,213.484 234.005,215.727 205.3,215.727 205.3,213.484
+15V_SN_L1 on Bottom Layer "Signal Layer 2-+15V_SN_L1" (solid, remove dead copper, pour order 1954): 172.581,267 172.581,264.758 210.997,264.758 210.997,267
-4V_SN_L1 on Bottom Layer "Signal Layer 2--4V_SN_L1" (solid, remove dead copper, pour order 1955): 172.581,264.758 172.581,258.243 211.011,258.243 211.011,264.758
VDC- on Bottom Layer "Bottom Layer-VDC- 2" (solid, remove dead copper, pour order 1946): 231.942,179.603 232.053,179.492 232.053,168.695 237.548,163.2 241.751,163.2 241.751,169.56 241.868,169.677 241.868,186.204 241.868,210.888 206.96,210.888 206.96,193.877 214.633,186.204 225.341,186.204
I_SN_L1- on Bottom Layer "Bottom Layer-I_SN_L1-" (solid, remove dead copper, pour order 1930): 17 vertices, not listed, extent 38.3,203.3 121.846,244.481
no net on Bottom Layer "Bottom Layer-No Net" (solid, remove dead copper, pour order 1906): 205.182,301.52
no net on Bottom Layer "Bottom Layer-No Net 1" (solid, remove dead copper, pour order 1905): 200.864,301.52
GND on Top Layer "TOP_LAYER_GND_P2224" (solid, remove dead copper, pour order 2224): 136 vertices, not listed, extent 0,0.407 270.1,345.207
+12V_FAN on Top Layer "TOP_LAYER_+12V_FAN_P2255" (solid, remove dead copper, pour order 2255): 127.24,318.668 128.768,318.668 128.768,316.679 127.24,316.679
+12V on Top Layer "TOP_LAYER_+12V_P2253" (solid, remove dead copper, pour order 2253): 124.943,320.929 126.47,320.929 126.47,318.94 124.943,318.94
FAN_SN on Top Layer "TOP_LAYER_FAN_SN_P2116" (solid, remove dead copper, pour order 2116): 134.2,311.3 139.8,311.3 139.8,308.068 134.2,308.068
+12V_FAN on Top Layer "TOP_LAYER_+12V_FAN_P2117" (solid, remove dead copper, pour order 2117): 143.898,313.1 163.4,313.1 163.4,305.6 143.898,305.6
+5V on Top Layer "TOP_LAYER_+5V_P2126" (solid, remove dead copper, pour order 2126): 105.402,326 114.002,326 114.002,327.1 117.102,327.1 117.102,325.6 116.104,324.601 116.104,315.5 112.402,315.5 112.402,321 105.402,321
SN_Relays on Top Layer "TOP_LAYER_SN_RELAYS_P2096" (solid, remove dead copper, pour order 2096): 85.7,44 85.7,41.4 86.498,41.4 86.5,39.34 84.3,39.34 84.3,44
AUX_IN_PWR on Top Layer "TOP_LAYER_AUX_IN_PWR_P2118" (solid, remove dead copper, pour order 2118): 87.067,333.985 87.702,333.35 87.702,332.6 89.302,331 90.702,331 90.702,332.722 86.025,337.4 86,337.375 83.202,337.375 83.202,344.614 77.412,344.614 77.412,333.985
VDC+ on Top Layer "Top Layer-REF_SN_L1" (solid, remove dead copper, pour order 2244): 159,27 159,21 152,21 152,27
V_SN_N on Top Layer "Top Layer-No Net" (solid, remove dead copper, pour order 2193): 42 vertices, not listed, extent 103.726,115.05 161.798,227.466
V_PCC_N on Top Layer "TOP_LAYER_V_PCC_N_P2095" (solid, pour order 2095): 17 vertices, not listed, extent 13.984,59.3 81.3,105.4
GRID_GND on Top Layer "TOP_LAYER_GRID_GND_P2144" (solid, remove dead copper, pour order 2144): 60.194,140.021 68.468,140.021 68.468,127.347 60.194,127.347
VDC-_REF on Top Layer "Top Layer-REF_SN_L1" (solid, remove dead copper, pour order 2227): 140.2,35 140.2,29.083 131.991,29.083 131.991,35
VDC-_REF on Top Layer "Top Layer-REF_SN_L1" (solid, remove dead copper, pour order 2228): 171.75,35.075 171.75,30 165,30 165,35.075
VDC-_REF on Top Layer "Top Layer-REF_SN_L1" (solid, remove dead copper, pour order 2064): 147.091,34.482 147.091,27.479 142.485,27.479 142.485,34.482
VINP_PCC_HAVOK on Top Layer "TOP_LAYER_VINP_PCC_HAVOK_P2225" (solid, pour order 2225): 71.26,102.61 71.26,104.398 64.611,104.398 64.611,102.61
VINP_SN_HAVOK on Top Layer "TOP_LAYER_VINP_SN_HAVOK_P2223" (solid, pour order 2223): 99.111,116.268 99.111,117.856 92.346,117.856 92.346,116.268
VINP_DC-_HAVOK on Top Layer "Top Layer-VINP_DC-_HAVOK" (solid, pour order 2222): 143.51,42.748 145.206,42.748 145.206,49.303 143.51,49.303
DESAT_BOT_L2 on Top Layer "Top Layer-REF_SN_L1" (solid, remove dead copper, pour order 2209): 209.165,182.001 209.19,178.207 205.863,178.207 205.863,182.001
VDC_MID on Top Layer "Top Layer-VDC_MID 3" (solid, remove dead copper, pour order 2185): 68 vertices, not listed, extent 129.998,2.017 267.92,314.7
VIN_PWR on Top Layer "Top Layer-VIN_PWR" (solid, pour order 2119): 18 vertices, not listed, extent 91.502,331.04 101.726,334.809
GRID_GND on Top Layer "TOP_LAYER_GRID_GND_P2143" (solid, remove dead copper, pour order 2143): 44.166,174.887 53.504,174.887 53.504,160.1 44.166,160.1
L2_MID_DRAIN on Top Layer "Top Layer-REF_SN_L1" (solid, remove dead copper, pour order 2221): 177.816,210.588 181.033,210.588 181.033,206.479 177.816,206.479
L2_MID_DRAIN on Top Layer "Top Layer-REF_SN_L1" (solid, remove dead copper, pour order 2220): 188.929,183.941 193.06,183.941 193.06,178.851 188.929,178.851
L3_MID_DRAIN on Top Layer "Top Layer-REF_SN_L1" (solid, remove dead copper, pour order 2219): 177.816,119.512 181.13,119.534 181.13,115.411 177.816,115.411
L3_MID_DRAIN on Top Layer "Top Layer-REF_SN_L1" (solid, remove dead copper, pour order 2218): 188.99,93.02 193.12,93.02 193.12,87.897 188.989,87.897
DESAT_BOT_L3 on Top Layer "Top Layer-REF_SN_L1" (solid, remove dead copper, pour order 2217): 199.578,121.483 203.99,121.513 203.99,116.386 199.578,116.386
DESAT_BOT_L2 on Top Layer "Top Layer-REF_SN_L1" (solid, remove dead copper, pour order 2214): 199.548,212.506 204.049,212.536 204.049,207.409 199.548,207.409
L1_MID_DRAIN on Top Layer "Top Layer-REF_SN_L1" (solid, remove dead copper, pour order 2213): 175.391,301.536 181.103,301.574 181.103,296.446 175.391,296.446
DESAT_BOT_L3 on Top Layer "Top Layer-REF_SN_L1" (solid, remove dead copper, pour order 2212): 186.257,95.961 186.311,87.858 182.18,87.858 182.18,95.961
DESAT_BOT_L2 on Top Layer "Top Layer-REF_SN_L1" (solid, remove dead copper, pour order 2211): 186.187,186.957 186.24,178.854 182.11,178.854 182.11,186.957
VDC- on Top Layer "Top Layer-VDC-" (solid, remove dead copper, pour order 1923): 203.286,110.004 204.723,111.441 215.993,111.441 215.993,115.546 213.94,117.6 207.334,117.6 203.332,113.599 199.005,113.599 199.005,110.004
VDC- on Top Layer "Top Layer-VDC- 1" (solid, remove dead copper, pour order 1918): 203.324,201.356 204.378,202.41 215.925,202.41 215.925,207.492 214.906,208.511 206.232,208.511 202.476,204.756 198.937,204.756 198.937,201.356
DESAT_BOT_L1 on Top Layer "Top Layer-REF_SN_L1" (solid, remove dead copper, pour order 2206): 186.139,278 186.192,269.897 182.062,269.897 182.062,278
VDC- on Top Layer "Top Layer-VDC- 2" (solid, remove dead copper, pour order 1912): 204.418,293.646 202.894,292.122 199.086,292.122 199.086,295.98 202.171,295.98 206.791,300.6 213.32,300.6 216.074,297.846 216.074,293.646
VDC_MID on Top Layer "Top Layer-VDC_MID 5" (solid, remove dead copper, pour order 1915): 180.941,289.029 184.429,285.541 192.513,285.496 196.047,281.962 206.477,281.962 206.477,289.557 206.452,289.582 199.164,289.582 196.546,292.2 196.546,295.678 188.672,295.678 188.041,296.309 186.166,298.184 186.166,301.462 180.941,301.462
DESAT_BOT_L3 on Top Layer "Top Layer-REF_SN_L1" (solid, remove dead copper, pour order 2210): 209.204,91.001 209.229,87.208 205.902,87.208 205.902,91.001
DESAT_BOT_L1 on Top Layer "Top Layer-REF_SN_L1" (solid, remove dead copper, pour order 2208): 209.212,272.938 209.252,266.835 205.91,266.835 205.91,272.938
L1_MID_DRAIN on Top Layer "Top Layer-REF_SN_L1" (solid, remove dead copper, pour order 2207): 192.387,278 192.442,269.776 189,269.776 189,278
DESAT_BOT_L1 on Top Layer "Top Layer-REF_SN_L1" (solid, remove dead copper, pour order 2205): 203.288,303.482 203.321,298.5 199.658,298.5 199.658,303.482
VDC_MID on Top Layer "Top Layer-VDC_MID 1" (solid, remove dead copper, pour order 1920): 165.812,213.342 165.812,195.683 167.59,195.683 185.194,195.683 185.194,203.617 178.631,203.621 168.914,213.342
VDC-_REF on Top Layer "Bottom Layer-REF_MID1" (solid, remove dead copper, pour order 2189): 121,6.5 121,0 130,0 130,3.218 126.718,6.5
AEF_CHK_2 on Top Layer "Top Layer-AEF_CHK_3" (solid, pour order 2184): 27.4,122.41 27.4,126.752 30.6,126.752 30.6,122.408
AEF_CHK_1 on Top Layer "Top Layer-AEF_CHK_3" (solid, pour order 2183): 27.473,154.658 27.473,159 30.673,159 30.673,154.656
AMC_HGND_L2 on Top Layer "TOP_LAYER_AMC_HGND_L2_P2089" (solid, remove dead copper, pour order 2089): 19.312,132.698 26.912,132.698 26.912,120.298 19.312,120.298
AEF_CHK_3 on Top Layer "Top Layer-AEF_CHK_3" (solid, pour order 2110): 27.366,138.472 27.366,142.67 30.566,142.67 30.566,138.47
AMC_HGND_L3 on Top Layer "TOP_LAYER_AMC_HGND_L3_P2087" (solid, remove dead copper, pour order 2087): 19.354,148.771 26.954,148.771 26.954,136.371 19.354,136.371
CHK_3 on Top Layer "Top Layer-CHK_3" (solid, pour order 2079): 29.541,91.341 30.299,92.1 34.826,96.626 34.826,125.29 27.929,132.187 27.929,137.8 34.3,137.8 34.3,136.6 34.826,136.074 38.781,136.119 46.367,128.533 46.367,92.484 40.283,86.4 26.9,86.4 26.9,88.701
AMC_HGND_L1 on Top Layer "TOP_LAYER_AMC_HGND_L1_P2091" (solid, remove dead copper, pour order 2091): 19.312,164.956 26.912,164.956 26.912,152.556 19.312,152.556
V_PCC_L3 on Top Layer "TOP_LAYER_V_PCC_L3_P2175" (solid, pour order 2175): 59.009,52.5 70.827,52.5 70.827,55 73.493,55 73.493,42 59.009,42
V_PCC_L2 on Top Layer "TOP_LAYER_V_PCC_L2_P2169" (solid, pour order 2169): 32.868,52.5 45.3,52.5 45.3,55 47.966,55 47.966,42 32.868,42
PCC_L3 on Top Layer "Top Layer-PCC_L1" (solid, pour order 2164): 86.985,25.978 65.985,25.978 65.985,1.978 86.985,1.978
PCC_L2 on Top Layer "Top Layer-PCC_L1" (solid, pour order 2160): 62.039,25.978 41.039,25.978 41.039,1.978 62.039,1.978
PCC_L1 on Top Layer "Top Layer-PCC_L1" (solid, pour order 2075): 36,26 15,26 15,2 36,2
I_SN_L3+ on Top Layer "Signal Layer 2-I_SN_L3+" (solid, pour order 2148): 118.892,61.248 121.546,61.253 127.034,66.741 106.31,87.465 99.457,80.683
CAN_GND1 on Top Layer "TOP_LAYER_CAN_GND1_P2141" (solid, remove dead copper, pour order 2141): 130.358,343.923 137.194,343.923 137.194,329.817 130.358,329.817
GND_ISO_CAN on Top Layer "TOP_LAYER_GND_ISO_CAN_P2139" (solid, remove dead copper, pour order 2139): 167.831,338.535 214.787,338.535 218.509,334.813 259.08,334.813 259.08,345 167.64,345 144.794,345 144.794,327.613 156.908,327.613
+5VISO_DC- on Top Layer "Top Layer-REF_SN_L1" (solid, remove dead copper, pour order 2065): 140.432,32.445 140.677,32.2 140.677,29.751 140.342,29.416 140.342,27.479 141.977,27.479 141.977,34.5 140.432,34.5
VDC_NEG_IN on Top Layer "Top Layer-VDC_NEG_IN" (solid, remove dead copper, pour order 1910): 136.589,27.077 146.256,27.077 146.256,19.439 143.024,16.206 136.589,22.641
+12V_OUT on Top Layer "TOP_LAYER_+12V_OUT_P2125" (solid, pour order 2125): 116.026,336 115.987,339.9 113.962,339.9 113.962,336 109.824,336 109.824,335.309 102.047,335.309 102.047,334.948 99.345,334.948 99.345,334.65 102.046,334.65 102.044,333.644 116.026,333.644
DCDC_VIN on Top Layer "TOP_LAYER_DCDC_VIN_P2124" (solid, pour order 2124): 116.302,333.316 116.902,332.716 116.902,330.9 117.402,330.4 117.394,327.818 117.743,327.818 118.308,328.382 118.54,328.382 118.54,335.746 118.202,336.083 116.302,336.083
GND on Top Layer "Top Layer-GND" (solid, pour order 2123): 100.846,335.162 100.846,335.95 101.959,337.063 101.959,340.497 101.11,340.497 101.11,337.377 100.62,336.887 100.62,335.162
+5VISO_SN on Top Layer "TOP_LAYER_+5VISO_SN_P2115" (solid, remove dead copper, pour order 2115): 108.995,112.7 109.406,112.7 110.503,113.796 113.162,113.796 113.162,115.05 107.162,115.05 107.162,112.7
